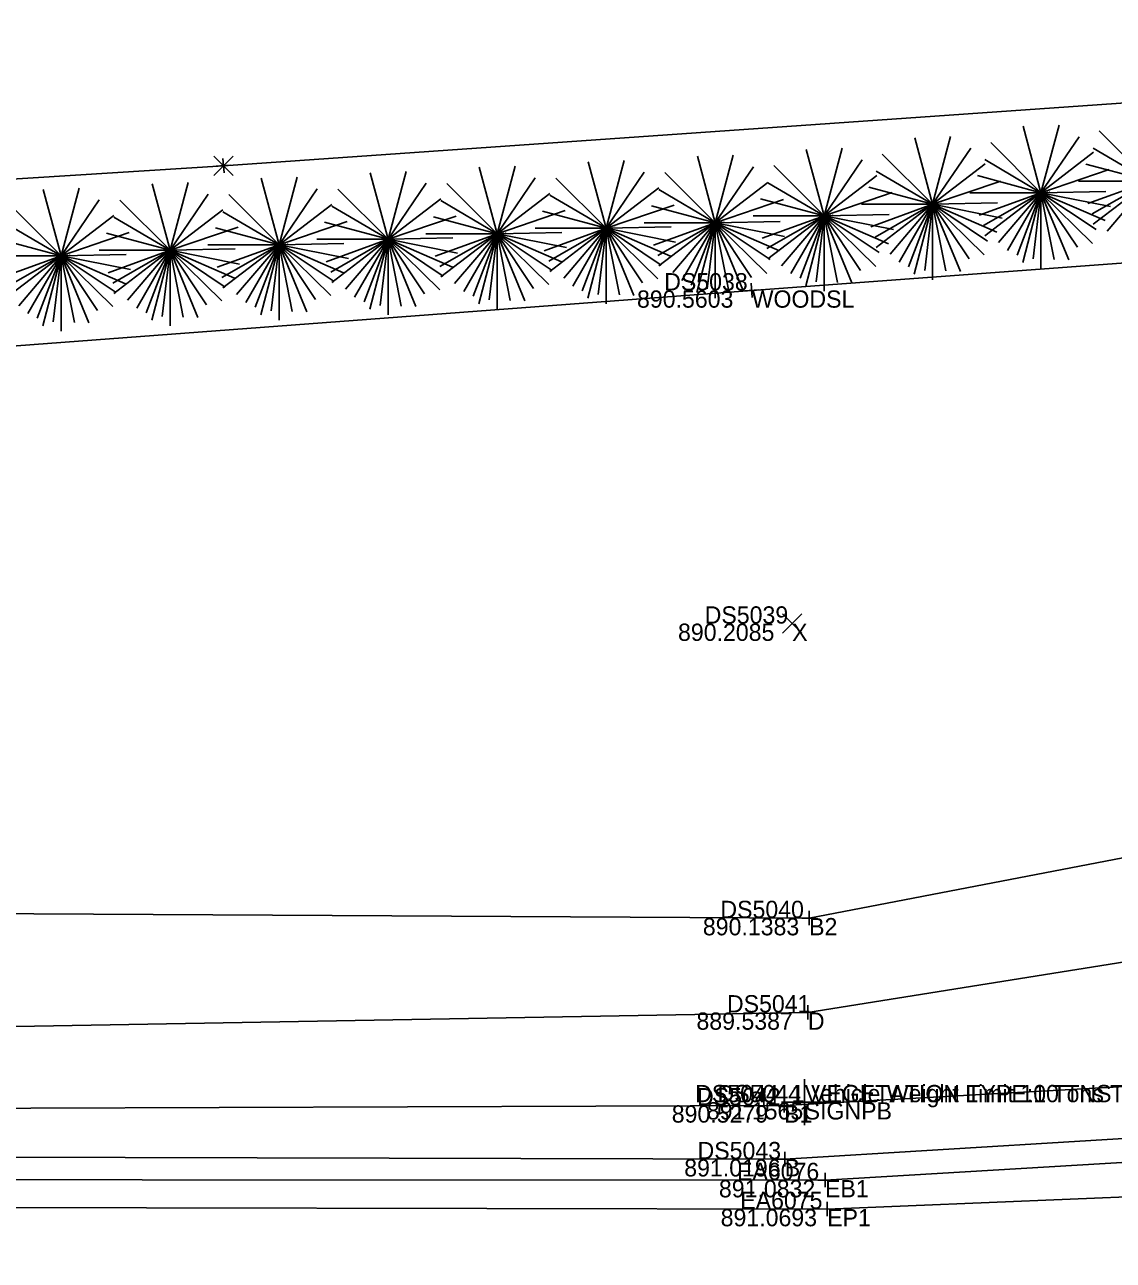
# Model space of a CAD drawing. Extents: x 179044 to 189691, y 286531 to 301257.
# Drawn here: x 180023.6 to 180099.2, y 300591.8 to 300677.6 of the extents above; entities that cross this region are included whole.
import ezdxf

# ---------------------------------------------------------------- set-up
doc = ezdxf.new("R2010")
doc.units = 0
for name, color, linetype in [('DR_X_Ditch', 7, 'Continuous'), ('PV_X_EOP', 7, 'Continuous'), ('PV_X_Shoulder_Aggregate', 7, 'Continuous'), ('RD_X_Fence', 7, 'Continuous'), ('SN_X_Public', 7, 'Continuous'), ('SV_X_Break_Lines', 7, 'Continuous'), ('SV_X_LiDAR_Check_Spots', 7, 'Continuous'), ('SV_X_Random_Point', 7, 'Continuous'), ('SV_X_Shot_Marker', 7, 'Continuous'), ('SV_X_Text_Comment', 7, 'Continuous'), ('SV_X_Text_Description', 7, 'Continuous'), ('SV_X_Text_Elevation', 7, 'Continuous'), ('SV_X_Text_Name', 7, 'Continuous'), ('VG_X_Cells', 7, 'Continuous'), ('VG_X_Text', 7, 'Continuous'), ('VG_X_Tree_Line_Rt', 7, 'Continuous')]:
    doc.layers.add(name, color=color, linetype=linetype)

msp = doc.modelspace()

# ---------------------------------------------------------------- linework, layer by layer
at = {"layer": 'DR_X_Ditch'}
msp.add_lwpolyline([(179564.56, 300599.962), (179672.339, 300603.26), (179771.172, 300605.494), (179880.337, 300606.441), (179984.937, 300607.328), (180077.947, 300608.965), (180127.19, 300616.843), (180132.045, 300619.573), (180144.286, 300623.545), (180155.547, 300629.29), (180160.465, 300633.547)], dxfattribs=at)
at = {"layer": 'PV_X_EOP'}
msp.add_lwpolyline([(179370.831, 300591.751), (179475.585, 300592.875), (179659.265, 300594.122), (179770.991, 300594.472), (179880.742, 300594.985), (179984.71, 300595.495), (180079.288, 300595.313), (180129.921, 300597.382), (180139.474, 300598.239), (180154.233, 300602.666), (180170.463, 300611.587), (180179.633, 300620.691), (180184.59, 300626.615), (180188.342, 300633.535), (180190.62, 300639.725), (180171.316, 300693.382), (180137.201, 300785.062), (180098.417, 300888.791)], dxfattribs=at)
at = {"layer": 'PV_X_Shoulder_Aggregate'}
msp.add_lwpolyline([(179563.565, 300594.924), (179658.987, 300595.359), (179770.596, 300596.259), (179881.565, 300597.129), (179984.257, 300597.357), (180079.139, 300597.322), (180129.307, 300600.299), (180139.964, 300601.425), (180153.02, 300605.118), (180169.97, 300613.883), (180177.635, 300623.691), (180181.654, 300635.111), (180182.998, 300649.235), (180167.771, 300692.69), (180134.639, 300784.201), (180095.484, 300888.508)], dxfattribs=at)
at = {"layer": 'RD_X_Fence'}
msp.add_lwpolyline([(180033.616, 300896.161), (180069.423, 300800.637), (180103.118, 300709.458), (180117.129, 300674.9), (180112.616, 300673.011), (180037.359, 300667.77), (179974.547, 300663.799), (179875.902, 300656.609), (179766.558, 300649.439), (179668.068, 300642.7), (179565.54, 300636.358)], dxfattribs=at)
at = {"layer": 'SN_X_Public'}
for p, q in [((180077.723, 300604.33), (180077.723, 300601.13)), ((180077.723, 300602.73), (180076.123, 300602.73))]:
    msp.add_line(p, q, dxfattribs=at)
at = {"layer": 'SV_X_Break_Lines'}
for points in [[(179564.638, 300606.986), (179671.768, 300606.922), (179771.087, 300608.912), (179880.599, 300615.611), (179986.884, 300616.02), (180078.033, 300615.521), (180124.742, 300624.492), (180128.289, 300624.221), (180137.303, 300629.118), (180148.459, 300633.708), (180154.503, 300636.496), (180146.307, 300651.241), (180135.969, 300673.811), (180118.542, 300716.074), (180095.911, 300772.35), (180076.611, 300824.96), (180047.5, 300900.199)], [(179564.191, 300598.682), (179770.809, 300601.942), (179880.33, 300600.557), (179984.707, 300602.17), (180076.298, 300602.513), (180129.447, 300605.473), (180133.823, 300610.665), (180143.543, 300612.063), (180154.911, 300619.358), (180168.807, 300625.749), (180172.898, 300631.66), (180174.527, 300641.071), (180168.307, 300660.619), (180157.537, 300688.57), (180123.865, 300779.294), (180087.271, 300883.216)], [(179564.385, 300595.92), (179672.75, 300596.68), (179770.459, 300597.562), (179880.51, 300598.544), (179984.703, 300599.007), (180076.342, 300598.773), (180129.476, 300602.027), (180135.94, 300603.814), (180151.807, 300606.879), (180162.976, 300612.722)]]:
    msp.add_lwpolyline(points, dxfattribs=at)
at = {"layer": 'SV_X_LiDAR_Check_Spots'}
for p, q in [((180077.723, 300604.23), (180077.723, 300601.23)), ((180076.223, 300602.73), (180079.223, 300602.73)), ((180077.723, 300602.73), (180077.723, 300602.73))]:
    msp.add_line(p, q, dxfattribs=at)
at = {"layer": 'SV_X_Random_Point'}
for p, q in [((180036.692, 300667.103), (180038.025, 300668.438)), ((180036.692, 300668.438), (180038.025, 300667.103)), ((180076.189, 300635.303), (180077.522, 300636.638)), ((180076.189, 300636.638), (180077.522, 300635.303))]:
    msp.add_line(p, q, dxfattribs=at)
at = {"layer": 'SV_X_Shot_Marker'}
for p, q in [((180037.399, 300667.272), (180037.319, 300668.269)), ((180037.857, 300667.81), (180036.86, 300667.73)), ((180037.359, 300667.77), (180037.359, 300667.77)), ((180074.007, 300659.611), (180074.082, 300658.614)), ((180073.546, 300659.075), (180074.543, 300659.15)), ((180074.045, 300659.112), (180074.045, 300659.112)), ((180077.533, 300615.524), (180078.533, 300615.518)), ((180078.036, 300616.021), (180078.031, 300615.021)), ((180078.033, 300615.521), (180078.033, 300615.521)), ((180077.938, 300609.465), (180077.955, 300608.465)), ((180077.447, 300608.956), (180078.447, 300608.973)), ((180077.947, 300608.965), (180077.947, 300608.965)), ((180076.296, 300603.013), (180076.3, 300602.013)), ((180075.798, 300602.511), (180076.798, 300602.515)), ((180076.298, 300602.513), (180076.298, 300602.513)), ((180076.343, 300599.273), (180076.341, 300598.273)), ((180075.842, 300598.775), (180076.842, 300598.772)), ((180076.342, 300598.773), (180076.342, 300598.773)), ((180079.139, 300597.822), (180079.138, 300596.822)), ((180078.639, 300597.323), (180079.638, 300597.322)), ((180079.139, 300597.322), (180079.139, 300597.322)), ((180079.289, 300595.813), (180079.287, 300594.813)), ((180078.788, 300595.314), (180079.788, 300595.312)), ((180079.288, 300595.313), (180079.288, 300595.313))]:
    msp.add_line(p, q, dxfattribs=at)
at = {"layer": 'VG_X_Cells'}
for p, q in [((180094.137, 300665.9), (180092.902, 300670.513)), ((180094.137, 300665.9), (180095.394, 300670.598)), ((180086.605, 300665.097), (180085.37, 300669.711)), ((180086.605, 300665.097), (180087.861, 300669.796)), ((180094.137, 300665.9), (180096.792, 300669.785)), ((180101.67, 300666.702), (180098.18, 300670.189)), ((180079.072, 300664.295), (180077.837, 300668.908)), ((180079.072, 300664.295), (180080.329, 300668.993)), ((180086.605, 300665.097), (180089.26, 300668.982)), ((180094.137, 300665.9), (180090.647, 300669.387)), ((180094.137, 300665.9), (180097.794, 300668.705)), ((180101.67, 300666.702), (180097.763, 300668.999)), ((180063.932, 300663.431), (180062.697, 300668.044)), ((180063.932, 300663.431), (180065.189, 300668.129)), ((180071.506, 300663.813), (180070.271, 300668.426)), ((180071.506, 300663.813), (180072.763, 300668.511)), ((180079.072, 300664.295), (180081.727, 300668.18)), ((180086.605, 300665.097), (180083.115, 300668.584)), ((180086.605, 300665.097), (180090.261, 300667.902)), ((180094.137, 300665.9), (180090.231, 300668.197)), ((180101.67, 300666.702), (180097.257, 300667.886)), ((180041.22, 300662.283), (180042.477, 300666.982)), ((180048.79, 300662.666), (180047.555, 300667.279)), ((180048.79, 300662.666), (180050.046, 300667.364)), ((180056.36, 300663.048), (180055.125, 300667.661)), ((180056.36, 300663.048), (180057.617, 300667.746)), ((180063.932, 300663.431), (180066.587, 300667.316)), ((180071.506, 300663.813), (180068.016, 300667.3)), ((180071.506, 300663.813), (180074.161, 300667.698)), ((180079.072, 300664.295), (180075.582, 300667.782)), ((180079.072, 300664.295), (180082.729, 300667.1)), ((180086.605, 300665.097), (180082.698, 300667.394)), ((180094.137, 300665.9), (180089.724, 300667.083)), ((180094.137, 300665.9), (180098.874, 300667.507)), ((180026.082, 300661.519), (180024.847, 300666.132)), ((180026.082, 300661.519), (180027.339, 300666.217)), ((180033.651, 300661.901), (180032.416, 300666.514)), ((180033.651, 300661.901), (180034.907, 300666.599)), ((180041.22, 300662.283), (180039.985, 300666.897)), ((180041.22, 300662.283), (180043.875, 300666.168)), ((180048.79, 300662.666), (180045.3, 300666.152)), ((180048.79, 300662.666), (180051.445, 300666.551)), ((180056.36, 300663.048), (180052.87, 300666.535)), ((180056.36, 300663.048), (180059.015, 300666.933)), ((180063.932, 300663.431), (180060.442, 300666.917)), ((180063.932, 300663.431), (180067.589, 300666.236)), ((180071.506, 300663.813), (180067.599, 300666.11)), ((180071.506, 300663.813), (180075.163, 300666.618)), ((180079.072, 300664.295), (180075.165, 300666.592)), ((180086.605, 300665.097), (180082.191, 300666.281)), ((180086.605, 300665.097), (180091.341, 300666.704)), ((180096.735, 300666.702), (180101.67, 300666.702)), ((180101.67, 300666.702), (180097.38, 300665.141)), ((180101.67, 300666.702), (180097.687, 300664.421)), ((180101.67, 300666.702), (180097.763, 300663.707)), ((180101.67, 300666.702), (180098.725, 300663.236)), ((180026.082, 300661.519), (180028.737, 300665.404)), ((180033.651, 300661.901), (180030.161, 300665.388)), ((180033.651, 300661.901), (180036.306, 300665.786)), ((180041.22, 300662.283), (180037.73, 300665.77)), ((180048.79, 300662.666), (180052.446, 300665.471)), ((180056.36, 300663.048), (180052.454, 300665.345)), ((180056.36, 300663.048), (180060.017, 300665.853)), ((180063.932, 300663.431), (180060.026, 300665.727)), ((180071.506, 300663.813), (180076.243, 300665.42)), ((180079.072, 300664.295), (180074.659, 300665.478)), ((180079.072, 300664.295), (180083.809, 300665.902)), ((180089.202, 300665.9), (180094.137, 300665.9)), ((180094.137, 300665.9), (180089.847, 300664.338)), ((180094.137, 300665.9), (180090.154, 300663.618)), ((180094.137, 300665.9), (180090.231, 300662.905)), ((180094.137, 300665.9), (180091.192, 300662.433)), ((180094.137, 300665.9), (180091.819, 300661.885)), ((180094.137, 300665.9), (180092.472, 300661.56)), ((180094.137, 300665.9), (180092.874, 300661.043)), ((180094.137, 300665.9), (180093.596, 300661.308)), ((180094.137, 300665.9), (180098.647, 300665.992)), ((180094.137, 300660.66), (180094.137, 300665.9)), ((180094.137, 300665.9), (180095.059, 300661.263)), ((180094.137, 300665.9), (180096.071, 300661.232)), ((180094.137, 300665.9), (180096.674, 300662.107)), ((180094.137, 300665.9), (180097.726, 300662.378)), ((180094.137, 300665.9), (180097.959, 300663.345)), ((180094.137, 300665.9), (180098.602, 300663.958)), ((180094.137, 300665.9), (180098.966, 300664.942)), ((180026.082, 300661.519), (180022.592, 300665.005)), ((180033.651, 300661.901), (180037.307, 300664.706)), ((180041.22, 300662.283), (180037.313, 300664.58)), ((180041.22, 300662.283), (180044.877, 300665.088)), ((180048.79, 300662.666), (180044.883, 300664.962)), ((180056.36, 300663.048), (180061.097, 300664.655)), ((180063.932, 300663.431), (180059.519, 300664.614)), ((180063.932, 300663.431), (180068.669, 300665.037)), ((180071.506, 300663.813), (180067.093, 300664.996)), ((180079.072, 300664.295), (180083.582, 300664.387)), ((180081.67, 300665.097), (180086.605, 300665.097)), ((180086.605, 300665.097), (180082.315, 300663.536)), ((180086.605, 300665.097), (180082.621, 300662.816)), ((180086.605, 300665.097), (180082.698, 300662.102)), ((180086.605, 300665.097), (180083.66, 300661.631)), ((180086.605, 300665.097), (180084.286, 300661.082)), ((180086.605, 300665.097), (180084.94, 300660.757)), ((180086.605, 300665.097), (180085.341, 300660.241)), ((180086.605, 300665.097), (180086.063, 300660.506)), ((180086.605, 300665.097), (180091.115, 300665.189)), ((180086.605, 300659.857), (180086.605, 300665.097)), ((180086.605, 300665.097), (180087.526, 300660.461)), ((180086.605, 300665.097), (180088.538, 300660.429)), ((180086.605, 300665.097), (180089.141, 300661.304)), ((180086.605, 300665.097), (180090.193, 300661.576)), ((180086.605, 300665.097), (180090.426, 300662.542)), ((180086.605, 300665.097), (180091.07, 300663.156)), ((180086.605, 300665.097), (180091.433, 300664.139)), ((180026.082, 300661.519), (180022.176, 300663.815)), ((180026.082, 300661.519), (180029.739, 300664.324)), ((180033.651, 300661.901), (180029.744, 300664.198)), ((180041.22, 300662.283), (180045.957, 300663.89)), ((180048.79, 300662.666), (180044.376, 300663.849)), ((180048.79, 300662.666), (180053.526, 300664.272)), ((180056.36, 300663.048), (180051.947, 300664.231)), ((180063.932, 300663.431), (180068.442, 300663.522)), ((180066.571, 300663.813), (180071.506, 300663.813)), ((180071.506, 300663.813), (180067.216, 300662.251)), ((180071.506, 300663.813), (180067.523, 300661.531)), ((180071.506, 300663.813), (180067.599, 300660.818)), ((180071.506, 300663.813), (180068.561, 300660.346)), ((180071.506, 300663.813), (180069.188, 300659.798)), ((180071.506, 300663.813), (180069.841, 300659.473)), ((180071.506, 300663.813), (180070.243, 300658.956)), ((180071.506, 300663.813), (180070.964, 300659.221)), ((180071.506, 300663.813), (180076.016, 300663.905)), ((180071.506, 300658.573), (180071.506, 300663.813)), ((180071.506, 300663.813), (180072.428, 300659.176)), ((180071.506, 300663.813), (180073.439, 300659.145)), ((180071.506, 300663.813), (180074.043, 300660.02)), ((180071.506, 300663.813), (180075.094, 300660.291)), ((180071.506, 300663.813), (180075.328, 300661.258)), ((180071.506, 300663.813), (180075.971, 300661.871)), ((180071.506, 300663.813), (180076.334, 300662.855)), ((180074.137, 300664.295), (180079.072, 300664.295)), ((180079.072, 300664.295), (180074.782, 300662.733)), ((180079.072, 300664.295), (180075.089, 300662.013)), ((180079.072, 300664.295), (180075.165, 300661.3)), ((180079.072, 300664.295), (180076.127, 300660.828)), ((180079.072, 300664.295), (180076.754, 300660.28)), ((180079.072, 300664.295), (180077.407, 300659.955)), ((180079.072, 300664.295), (180077.809, 300659.438)), ((180079.072, 300664.295), (180078.53, 300659.703)), ((180079.072, 300659.055), (180079.072, 300664.295)), ((180079.072, 300664.295), (180079.994, 300659.658)), ((180079.072, 300664.295), (180081.005, 300659.627)), ((180079.072, 300664.295), (180081.609, 300660.502)), ((180079.072, 300664.295), (180082.66, 300660.773)), ((180079.072, 300664.295), (180082.894, 300661.74)), ((180079.072, 300664.295), (180083.537, 300662.353)), ((180079.072, 300664.295), (180083.9, 300663.337)), ((180026.082, 300661.519), (180021.669, 300662.702)), ((180026.082, 300661.519), (180030.819, 300663.125)), ((180033.651, 300661.901), (180029.237, 300663.084)), ((180033.651, 300661.901), (180038.387, 300663.508)), ((180041.22, 300662.283), (180036.807, 300663.467)), ((180043.855, 300662.666), (180048.79, 300662.666)), ((180048.79, 300662.666), (180044.5, 300661.104)), ((180048.79, 300662.666), (180044.806, 300660.384)), ((180048.79, 300662.666), (180044.883, 300659.671)), ((180048.79, 300662.666), (180045.845, 300659.199)), ((180048.79, 300662.666), (180046.471, 300658.651)), ((180048.79, 300662.666), (180047.125, 300658.326)), ((180048.79, 300662.666), (180047.526, 300657.809)), ((180048.79, 300662.666), (180048.248, 300658.074)), ((180048.79, 300662.666), (180053.3, 300662.757)), ((180048.79, 300657.426), (180048.79, 300662.666)), ((180048.79, 300662.666), (180049.711, 300658.029)), ((180048.79, 300662.666), (180050.723, 300657.997)), ((180048.79, 300662.666), (180051.326, 300658.872)), ((180048.79, 300662.666), (180052.378, 300659.144)), ((180048.79, 300662.666), (180052.611, 300660.111)), ((180048.79, 300662.666), (180053.255, 300660.724)), ((180048.79, 300662.666), (180053.618, 300661.707)), ((180051.425, 300663.048), (180056.36, 300663.048)), ((180056.36, 300663.048), (180052.07, 300661.486)), ((180056.36, 300663.048), (180052.377, 300660.766)), ((180056.36, 300663.048), (180052.454, 300660.053)), ((180056.36, 300663.048), (180053.415, 300659.581)), ((180056.36, 300663.048), (180054.042, 300659.033)), ((180056.36, 300663.048), (180054.695, 300658.708)), ((180056.36, 300663.048), (180055.097, 300658.191)), ((180056.36, 300663.048), (180055.819, 300658.456)), ((180056.36, 300663.048), (180060.87, 300663.14)), ((180056.36, 300657.808), (180056.36, 300663.048)), ((180056.36, 300663.048), (180057.282, 300658.411)), ((180056.36, 300663.048), (180058.294, 300658.38)), ((180056.36, 300663.048), (180058.897, 300659.255)), ((180056.36, 300663.048), (180059.949, 300659.526)), ((180056.36, 300663.048), (180060.182, 300660.493)), ((180056.36, 300663.048), (180060.825, 300661.106)), ((180056.36, 300663.048), (180061.189, 300662.09)), ((180058.997, 300663.431), (180063.932, 300663.431)), ((180063.932, 300663.431), (180059.642, 300661.869)), ((180063.932, 300663.431), (180059.949, 300661.149)), ((180063.932, 300663.431), (180060.026, 300660.436)), ((180063.932, 300663.431), (180060.987, 300659.964)), ((180063.932, 300663.431), (180061.614, 300659.416)), ((180063.932, 300663.431), (180062.267, 300659.091)), ((180063.932, 300663.431), (180062.669, 300658.574)), ((180063.932, 300663.431), (180063.391, 300658.839)), ((180063.932, 300658.191), (180063.932, 300663.431)), ((180063.932, 300663.431), (180064.854, 300658.794)), ((180063.932, 300663.431), (180065.866, 300658.762)), ((180063.932, 300663.431), (180066.469, 300659.637)), ((180063.932, 300663.431), (180067.521, 300659.909)), ((180063.932, 300663.431), (180067.754, 300660.876)), ((180063.932, 300663.431), (180068.397, 300661.489)), ((180063.932, 300663.431), (180068.761, 300662.472)), ((180028.716, 300661.901), (180033.651, 300661.901)), ((180033.651, 300661.901), (180029.361, 300660.339)), ((180033.651, 300661.901), (180029.667, 300659.619)), ((180033.651, 300661.901), (180029.744, 300658.906)), ((180033.651, 300661.901), (180030.706, 300658.434)), ((180033.651, 300661.901), (180031.332, 300657.886)), ((180033.651, 300661.901), (180031.986, 300657.561)), ((180033.651, 300661.901), (180032.387, 300657.044)), ((180033.651, 300661.901), (180033.109, 300657.309)), ((180033.651, 300661.901), (180038.161, 300661.993)), ((180033.651, 300656.661), (180033.651, 300661.901)), ((180033.651, 300661.901), (180034.572, 300657.264)), ((180033.651, 300661.901), (180035.584, 300657.233)), ((180033.651, 300661.901), (180036.187, 300658.108)), ((180033.651, 300661.901), (180037.239, 300658.379)), ((180033.651, 300661.901), (180037.472, 300659.346)), ((180033.651, 300661.901), (180038.116, 300659.959)), ((180033.651, 300661.901), (180038.479, 300660.943)), ((180036.285, 300662.283), (180041.22, 300662.283)), ((180041.22, 300662.283), (180036.93, 300660.722)), ((180041.22, 300662.283), (180037.237, 300660.002)), ((180041.22, 300662.283), (180037.313, 300659.288)), ((180041.22, 300662.283), (180038.275, 300658.817)), ((180041.22, 300662.283), (180038.902, 300658.268)), ((180041.22, 300662.283), (180039.555, 300657.943)), ((180041.22, 300662.283), (180039.957, 300657.427)), ((180041.22, 300662.283), (180040.678, 300657.692)), ((180041.22, 300662.283), (180045.73, 300662.375)), ((180041.22, 300657.043), (180041.22, 300662.283)), ((180041.22, 300662.283), (180042.142, 300657.647)), ((180041.22, 300662.283), (180043.153, 300657.615)), ((180041.22, 300662.283), (180043.757, 300658.49)), ((180041.22, 300662.283), (180044.808, 300658.762)), ((180041.22, 300662.283), (180045.042, 300659.728)), ((180041.22, 300662.283), (180045.685, 300660.342)), ((180041.22, 300662.283), (180046.048, 300661.325)), ((180021.147, 300661.519), (180026.082, 300661.519)), ((180026.082, 300661.519), (180021.792, 300659.957)), ((180026.082, 300661.519), (180022.099, 300659.237)), ((180026.082, 300661.519), (180022.176, 300658.524)), ((180026.082, 300661.519), (180023.137, 300658.052)), ((180026.082, 300661.519), (180023.764, 300657.504)), ((180026.082, 300661.519), (180024.417, 300657.179)), ((180026.082, 300661.519), (180024.819, 300656.662)), ((180026.082, 300661.519), (180025.541, 300656.927)), ((180026.082, 300661.519), (180030.592, 300661.61)), ((180026.082, 300656.279), (180026.082, 300661.519)), ((180026.082, 300661.519), (180027.004, 300656.882)), ((180026.082, 300661.519), (180028.016, 300656.85)), ((180026.082, 300661.519), (180028.619, 300657.725)), ((180026.082, 300661.519), (180029.671, 300657.997)), ((180026.082, 300661.519), (180029.904, 300658.964)), ((180026.082, 300661.519), (180030.547, 300659.577)), ((180026.082, 300661.519), (180030.911, 300660.56))]:
    msp.add_line(p, q, dxfattribs=at)
at = {"layer": 'VG_X_Tree_Line_Rt'}
msp.add_lwpolyline([(179653.026, 300638.702), (179657.624, 300631.959), (179767.935, 300639.504), (179876.981, 300645.549), (179982.655, 300652.223), (180074.045, 300659.112), (180113.167, 300662.01), (180119.55, 300662.124), (180124.383, 300666.201), (180126.147, 300679.098), (180114.54, 300714.374), (180093.362, 300771.604), (180073.514, 300824.308), (180043.465, 300899.612)], dxfattribs=at)

# ---------------------------------------------------------------- texts
at = {"layer": 'SV_X_Text_Comment'}
for s, height, p in [('X', 0.06, (180037.359, 300667.71)), ('FEN', 0.06, (180037.359, 300667.71)), ('TE', 0.12, (180094.137, 300665.78)), ('TE', 0.12, (180086.605, 300664.977)), ('TE', 0.12, (180071.506, 300663.693)), ('TE', 0.12, (180079.072, 300664.175)), ('TE', 0.12, (180048.79, 300662.546)), ('TE', 0.12, (180056.36, 300662.928)), ('TE', 0.12, (180063.932, 300663.311)), ('TE', 0.12, (180033.651, 300661.781)), ('TE', 0.12, (180041.22, 300662.163)), ('TE', 0.12, (180026.082, 300661.399)), ('WOODSL', 1.2, (180074.045, 300657.912)), ('X', 1.2, (180076.856, 300634.771)), ('B2', 1.2, (180078.033, 300614.321)), ('D', 1.2, (180077.947, 300607.765)), ('S', 1.2, (180077.723, 300601.53)), ('SIGNPB', 1.2, (180077.723, 300601.53)), ('B1', 1.2, (180076.298, 300601.313)), ('B', 1.2, (180076.342, 300597.573)), ('EB1', 1.2, (180079.139, 300596.122)), ('EP1', 1.2, (180079.288, 300594.113))]:
    msp.add_text(s, height=height, dxfattribs=at).set_placement(p)
at = {"layer": 'SV_X_Text_Description'}
for s in ['Vehicle Weight Limit 10 Tons TYPE:', ' VEGETATION TYPE:10 TNS']:
    msp.add_text(s, height=1.2, dxfattribs=at).set_placement((180077.723, 300602.73))
at = {"layer": 'SV_X_Text_Elevation'}
for s, height, p in [('890.8530', 0.06, (180036.961, 300667.71)), ('890.8530', 0.06, (180036.961, 300667.71)), ('890.5603', 1.2, (180066.08, 300657.912)), ('890.2085', 1.2, (180068.929, 300634.771)), ('890.1383', 1.2, (180070.655, 300614.321)), ('889.5387', 1.2, (180070.209, 300607.765)), ('891.1565', 1.2, (180070.931, 300601.53)), ('891.1565', 1.2, (180070.931, 300601.53)), ('890.5279', 1.2, (180068.494, 300601.313)), ('891.0196', 1.2, (180069.361, 300597.573)), ('891.0832', 1.2, (180071.769, 300596.122)), ('891.0693', 1.2, (180071.891, 300594.113))]:
    msp.add_text(s, height=height, dxfattribs=at).set_placement(p)
at = {"layer": 'SV_X_Text_Name'}
for s, height, p in [('SV5032_1', 0.06, (180036.997, 300667.77)), ('SV5032', 0.06, (180037.055, 300667.77)), ('DS5038', 1.2, (180067.969, 300659.112)), ('DS5039', 1.2, (180070.781, 300635.971)), ('DS5040', 1.2, (180071.873, 300615.521)), ('DS5041', 1.2, (180072.328, 300608.965)), ('DS5044_1', 1.2, (180070.12, 300602.73)), ('DS5042', 1.2, (180070.252, 300602.513)), ('DS5044', 1.2, (180071.676, 300602.73)), ('DS5043', 1.2, (180070.286, 300598.773)), ('EA6076', 1.2, (180073.026, 300597.322)), ('EA6075', 1.2, (180073.251, 300595.313))]:
    msp.add_text(s, height=height, dxfattribs=at).set_placement(p)
at = {"layer": 'VG_X_Text'}
for p in [(180094.137, 300665.9), (180079.072, 300664.295), (180086.605, 300665.097), (180063.932, 300663.431), (180071.506, 300663.813), (180048.79, 300662.666), (180056.36, 300663.048), (180033.651, 300661.901), (180041.22, 300662.283), (180026.082, 300661.519)]:
    msp.add_text(' NOTE:8', height=0.12, dxfattribs=at).set_placement(p)

doc.saveas('drawing.dxf')
